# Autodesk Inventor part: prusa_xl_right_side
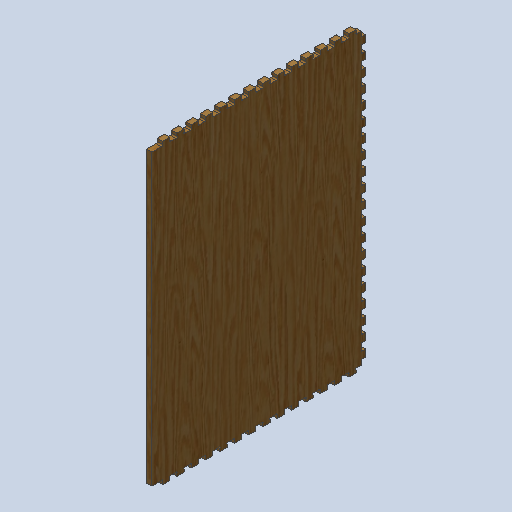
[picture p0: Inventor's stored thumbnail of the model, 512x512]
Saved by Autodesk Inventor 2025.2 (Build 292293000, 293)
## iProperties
Created: 2024-11
Part Number: prusa_xl_right_side
Material: Plywood, Finish
Document SubType Name: Modeling
Designer: BennF
Density: 0.552 g/cm^3
Appearance: Plywood - New
Author: BennF
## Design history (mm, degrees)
sketch "Sketch2"
  geometry: L1 (-351, 484.5)-(351, 484.5); L2 (351, 484.5)-(351, -484.5); L3 (351, -484.5)-(-351, -484.5); L4 (-351, -484.5)-(-351, 484.5); 3 further points
  constraints: 8 end point, 2 midpoint, 2 parallel, 1 horizontal, 1 horizontal alignment, 1 perpendicular, 1 vertical alignment
  dimensions: "d0" = 702 distance of L1.start L1.end (= prusa_xl_depth - finger_depth); "d1" = 969 distance of L3.end L1.start (= prusa_xl_height - 2 x finger_depth)
extrude "base_material" new body sketch "Sketch2" distance "d2" = 18 (= thickness); taper "d3" = 0 deg
sketch "Sketch3"
  geometry: L1 (-484.5, -314.9)-(-498, -314.9); L2 (-498, -314.9)-(-498, -291.1); L3 (-498, -291.1)-(-484.5, -291.1); L4 (0, -351)-(0, 351); L5 (-467.9, 351)-(-467.9, 364.5); L6 (-467.9, 364.5)-(-444.1, 364.5); L7 (-444.1, 364.5)-(-444.1, 351); L8 (-484.5, -266.9)-(-498, -266.9); L9 (-498, -266.9)-(-498, -243.1); L10 (-498, -243.1)-(-484.5, -243.1); L11 (-484.5, -218.9)-(-498, -218.9); L12 (-498, -218.9)-(-498, -195.1); L13 (-498, -195.1)-(-484.5, -195.1); L14 (-484.5, -170.9)-(-498, -170.9); L15 (-498, -170.9)-(-498, -147.1); L16 (-498, -147.1)-(-484.5, -147.1); L17 (-484.5, -122.9)-(-498, -122.9); L18 (-498, -122.9)-(-498, -99.1); L19 (-498, -99.1)-(-484.5, -99.1); L20 (-484.5, -74.9)-(-498, -74.9); L21 (-498, -74.9)-(-498, -51.1); L22 (-498, -51.1)-(-484.5, -51.1); L23 (-484.5, -26.9)-(-498, -26.9); L24 (-498, -26.9)-(-498, -3.1); L25 (-498, -3.1)-(-484.5, -3.1); L26 (-484.5, 21.1)-(-498, 21.1); L27 (-498, 21.1)-(-498, 44.9); L28 (-498, 44.9)-(-484.5, 44.9); L29 (-484.5, 69.1)-(-498, 69.1); L30 (-498, 69.1)-(-498, 92.9); L31 (-498, 92.9)-(-484.5, 92.9); L32 (-484.5, 117.1)-(-498, 117.1); L33 (-498, 117.1)-(-498, 140.9); L34 (-498, 140.9)-(-484.5, 140.9); L35 (-484.5, 165.1)-(-498, 165.1); L36 (-498, 165.1)-(-498, 188.9); L37 (-498, 188.9)-(-484.5, 188.9); L38 (-484.5, 213.1)-(-498, 213.1); L39 (-498, 213.1)-(-498, 236.9); L40 (-498, 236.9)-(-484.5, 236.9); L41 (-484.5, 261.1)-(-498, 261.1); L42 (-498, 261.1)-(-498, 284.9); L43 (-498, 284.9)-(-484.5, 284.9); L44 (-484.5, 309.1)-(-498, 309.1); L45 (-498, 309.1)-(-498, 332.9); L46 (-498, 332.9)-(-484.5, 332.9); L47 (498, 236.9)-(484.5, 236.9); L48 (484.5, 213.1)-(498, 213.1); L49 (498, 213.1)-(498, 236.9); L50 (498, 188.9)-(484.5, 188.9); L51 (484.5, 165.1)-(498, 165.1); L52 (498, 165.1)-(498, 188.9); L53 (484.5, 261.1)-(498, 261.1); L54 (498, 261.1)-(498, 284.9); L55 (498, 284.9)-(484.5, 284.9); L56 (484.5, 309.1)-(498, 309.1); L57 (498, 309.1)-(498, 332.9); L58 (498, 332.9)-(484.5, 332.9); L59 (484.5, -170.9)-(498, -170.9); L60 (498, -170.9)-(498, -147.1); L61 (498, -147.1)-(484.5, -147.1); L62 (484.5, -122.9)-(498, -122.9); L63 (498, -122.9)-(498, -99.1); L64 (498, -99.1)-(484.5, -99.1)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; 103 further points
  constraints: 290 end point, 76 horizontal alignment, 64 parallel, 59 symmetric about line, 52 vertical alignment, 32 collinear, 4 perpendicular, 1 horizontal, 1 midpoint, 1 vertical, 13 other
  dimensions: "d4" = 23.8 distance of L1.end L2.end (derived); "d13" = 23.8 distance of L5.end L6.end (derived); "d22" = 13.5 distance of L1.start L1.end (derived); "d23" = 13.5 distance of L5.start L5.end (derived); "d26" = 48 distance of L1.start L8.start (= finger_distance); "d33" = 48 distance of L5.start L91.start (= finger_distance); "d40" = 36.1 distance between parallel lines of L90 L1 (derived); "d41" = 30.1 distance between parallel lines of L5 L45 (derived)
extrude "joints_1" join sketch "Sketch3" distance "d38" = 18 (= thickness); taper "d39" = 0 deg
sketch "Sketch5"
  geometry: L1 (-40.167, -315)-(-21.967, -315); L2 (-21.967, -315)-(-21.967, -291); L3 (-21.967, -291)-(-40.167, -291); L4 (-40.167, -291)-(-40.167, -315); L5 (-484.5, -314.9)-(-484.5, -351) reference; L6 (222.367, -315)-(240.567, -315); L7 (240.567, -315)-(240.567, -291); L8 (240.567, -291)-(222.367, -291); L9 (222.367, -291)-(222.367, -315); L10 (-40.167, -267)-(-21.967, -267); L11 (-40.167, -243)-(-40.167, -267); L12 (-21.967, -243)-(-40.167, -243); L13 (-21.967, -267)-(-21.967, -243); L14 (222.367, -243)-(222.367, -267); L15 (222.367, -267)-(240.567, -267); L16 (240.567, -267)-(240.567, -243); L17 (240.567, -243)-(222.367, -243); L18 (-40.167, -219)-(-21.967, -219); L19 (-40.167, -195)-(-40.167, -219); L20 (-21.967, -195)-(-40.167, -195); L21 (-21.967, -219)-(-21.967, -195); L22 (222.367, -195)-(222.367, -219); L23 (222.367, -219)-(240.567, -219); L24 (240.567, -219)-(240.567, -195); L25 (240.567, -195)-(222.367, -195); L26 (-40.167, -171)-(-21.967, -171); L27 (-40.167, -147)-(-40.167, -171); L28 (-21.967, -147)-(-40.167, -147); L29 (-21.967, -171)-(-21.967, -147); L30 (222.367, -147)-(222.367, -171); L31 (222.367, -171)-(240.567, -171); L32 (240.567, -171)-(240.567, -147); L33 (240.567, -147)-(222.367, -147); L34 (-40.167, -123)-(-21.967, -123); L35 (-40.167, -99)-(-40.167, -123); L36 (-21.967, -99)-(-40.167, -99); L37 (-21.967, -123)-(-21.967, -99); L38 (222.367, -99)-(222.367, -123); L39 (222.367, -123)-(240.567, -123); L40 (240.567, -123)-(240.567, -99); L41 (240.567, -99)-(222.367, -99); L42 (-40.167, -75)-(-21.967, -75); L43 (-40.167, -51)-(-40.167, -75); L44 (-21.967, -51)-(-40.167, -51); L45 (-21.967, -75)-(-21.967, -51); L46 (222.367, -51)-(222.367, -75); L47 (222.367, -75)-(240.567, -75); L48 (240.567, -75)-(240.567, -51); L49 (240.567, -51)-(222.367, -51); L50 (-40.167, -27)-(-21.967, -27); L51 (-40.167, -3)-(-40.167, -27); L52 (-21.967, -3)-(-40.167, -3); L53 (-21.967, -27)-(-21.967, -3); L54 (222.367, -3)-(222.367, -27); L55 (222.367, -27)-(240.567, -27); L56 (240.567, -27)-(240.567, -3); L57 (240.567, -3)-(222.367, -3); L58 (-40.167, 21)-(-21.967, 21); L59 (-40.167, 45)-(-40.167, 21); L60 (-21.967, 45)-(-40.167, 45); L61 (-21.967, 21)-(-21.967, 45); L62 (222.367, 45)-(222.367, 21); L63 (222.367, 21)-(240.567, 21); L64 (240.567, 21)-(240.567, 45)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; 1 further point
  constraints: 224 end point, 4 parallel, 2 equal length, 2 horizontal, 2 perpendicular, 1 collinear, 1 horizontal alignment, 1 vertical, 207 other
  dimensions: "d59" = 24 distance of L3.end L1.start (= finger_width); "d60" = 18.2 distance of L1.start L1.end (derived); "d61" = 444.33333 distance between parallel lines of L5 L4 (= box_clearence_1 + box_height_1); "d62" = 244.33333 distance from line of L8.end L2 (= box_clearence_1 + box_height_2); "d65" = 48 distance of L1.start L10.start (= finger_distance); "d70" = 36 distance between parallel lines of L1 L114 (derived)
  node "Sketch Rectangular Pattern7" dims "d65" = 48 (= finger_distance), "d68" = 10
extrude "joints_2" cut sketch "Sketch5" distance "d71" = 13.5 (derived); taper "d72" = 0 deg
sketch "Sketch4" dims "d42" = 6 (= dogbone_diameter)
  geometry: L1 (484.5, -351)-(484.5, -314.9) reference; L2 (484.5, -314.9)-(498, -314.9) reference; L3 (498, -314.9)-(498, -291.1) reference; L4 (498, -291.1)-(484.5, -291.1) reference; L5 (484.5, -291.1)-(484.5, -266.9) reference; L6 (484.5, -266.9)-(498, -266.9) reference; L7 (498, -266.9)-(498, -243.1) reference; L8 (498, -243.1)-(484.5, -243.1) reference; L9 (484.5, -243.1)-(484.5, -218.9) reference; L10 (484.5, -218.9)-(498, -218.9) reference; L11 (498, -218.9)-(498, -195.1) reference; L12 (498, -195.1)-(484.5, -195.1) reference; L13 (484.5, -195.1)-(484.5, -170.9) reference; L14 (484.5, -170.9)-(498, -170.9) reference; L15 (498, -170.9)-(498, -147.1) reference; L16 (498, -147.1)-(484.5, -147.1) reference; L17 (484.5, -147.1)-(484.5, -122.9) reference; L18 (484.5, -122.9)-(498, -122.9) reference; L19 (498, -122.9)-(498, -99.1) reference; L20 (498, -99.1)-(484.5, -99.1) reference; L21 (484.5, -99.1)-(484.5, -74.9) reference; L22 (484.5, -74.9)-(498, -74.9) reference; L23 (498, -74.9)-(498, -51.1) reference; L24 (498, -51.1)-(484.5, -51.1) reference; L25 (484.5, -51.1)-(484.5, -26.9) reference; L26 (484.5, -26.9)-(498, -26.9) reference; L27 (498, -26.9)-(498, -3.1) reference; L28 (498, -3.1)-(484.5, -3.1) reference; L29 (484.5, -3.1)-(484.5, 21.1) reference; L30 (484.5, 21.1)-(498, 21.1) reference; L31 (498, 21.1)-(498, 44.9) reference; L32 (498, 44.9)-(484.5, 44.9) reference; L33 (484.5, 44.9)-(484.5, 69.1) reference; L34 (484.5, 69.1)-(498, 69.1) reference; L35 (498, 69.1)-(498, 92.9) reference; L36 (498, 92.9)-(484.5, 92.9) reference; L37 (484.5, 92.9)-(484.5, 117.1) reference; L38 (484.5, 117.1)-(498, 117.1) reference; L39 (498, 117.1)-(498, 140.9) reference; L40 (498, 140.9)-(484.5, 140.9) reference; L41 (484.5, 140.9)-(484.5, 165.1) reference; L42 (484.5, 165.1)-(498, 165.1) reference; L43 (498, 165.1)-(498, 188.9) reference; L44 (498, 188.9)-(484.5, 188.9) reference; L45 (484.5, 188.9)-(484.5, 213.1) reference; L46 (484.5, 213.1)-(498, 213.1) reference; L47 (498, 213.1)-(498, 236.9) reference; L48 (498, 236.9)-(484.5, 236.9) reference; L49 (484.5, 236.9)-(484.5, 261.1) reference; L50 (484.5, 261.1)-(498, 261.1) reference; L51 (498, 261.1)-(498, 284.9) reference; L52 (498, 284.9)-(484.5, 284.9) reference; L53 (484.5, 284.9)-(484.5, 309.1) reference; L54 (484.5, 309.1)-(498, 309.1) reference; L55 (498, 309.1)-(498, 332.9) reference; L56 (498, 332.9)-(484.5, 332.9) reference; L57 (484.5, 332.9)-(484.5, 351) reference; L58 (484.5, 351)-(467.9, 351) reference; L59 (467.9, 351)-(467.9, 364.5) reference; L60 (467.9, 364.5)-(444.1, 364.5) reference; L61 (444.1, 364.5)-(444.1, 351) reference; L62 (444.1, 351)-(419.9, 351) reference; L63 (419.9, 351)-(419.9, 364.5) reference; L64 (419.9, 364.5)-(396.1, 364.5) reference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; 258 further points
  constraints: 204 end point, 134 symmetric about line, 56 vertical, 40 horizontal, 30 point on line, 6 midpoint, 4 perpendicular, 2 collinear, 2 horizontal alignment, 2 vertical alignment, 598 other
  dimensions: "d45" = 48 distance of L190.end L202.end (= finger_distance); "d52" = 48 distance of point (-441.979, 353.121) point (-393.979, 353.121) (= finger_distance)
extrude "dogbones_1" cut sketch "Sketch4" distance "d57" = 18 (= thickness); taper "d58" = 0 deg
sketch "Sketch6" dims "d80" = 6 (derived)
  geometry: L1 (-488.743, -195.1)-(-498, -195.1) reference; L2 (-498, -195.1)-(-498, -218.9) reference; L3 (-498, -218.9)-(-488.743, -218.9) reference; L4 (-484.5, -223.143)-(-484.5, -238.857) reference; L5 (-488.743, -243.1)-(-498, -243.1) reference; L6 (-498, -243.1)-(-498, -266.9) reference; L7 (-498, -266.9)-(-488.743, -266.9) reference; L8 (-484.5, -271.143)-(-484.5, -286.857) reference; L9 (-488.743, -291.1)-(-498, -291.1) reference; L10 (-498, -291.1)-(-498, -314.9) reference; L11 (-498, -314.9)-(-488.743, -314.9) reference; L12 (-484.5, -319.143)-(-484.5, -351) reference; L13 (-484.5, -351)-(484.5, -351) reference; L14 (484.5, -351)-(484.5, -319.143) reference; L15 (488.743, -314.9)-(498, -314.9) reference; L16 (498, -314.9)-(498, -291.1) reference; L17 (498, -291.1)-(488.743, -291.1) reference; L18 (484.5, -286.857)-(484.5, -271.143) reference; L19 (488.743, -266.9)-(498, -266.9) reference; L20 (498, -266.9)-(498, -243.1) reference; L21 (498, -243.1)-(488.743, -243.1) reference; L22 (484.5, -238.857)-(484.5, -223.143) reference; L23 (488.743, -218.9)-(498, -218.9) reference; L24 (498, -218.9)-(498, -195.1) reference; L25 (498, -195.1)-(488.743, -195.1) reference; L26 (484.5, -190.857)-(484.5, -175.143) reference; L27 (488.743, -170.9)-(498, -170.9) reference; L28 (498, -170.9)-(498, -147.1) reference; L29 (498, -147.1)-(488.743, -147.1) reference; L30 (484.5, -142.857)-(484.5, -127.143) reference; L31 (488.743, -122.9)-(498, -122.9) reference; L32 (498, -122.9)-(498, -99.1) reference; L33 (498, -99.1)-(488.743, -99.1) reference; L34 (484.5, -94.857)-(484.5, -79.143) reference; L35 (488.743, -74.9)-(498, -74.9) reference; L36 (498, -74.9)-(498, -51.1) reference; L37 (498, -51.1)-(488.743, -51.1) reference; L38 (484.5, -46.857)-(484.5, -31.143) reference; L39 (488.743, -26.9)-(498, -26.9) reference; L40 (498, -26.9)-(498, -3.1) reference; L41 (498, -3.1)-(488.743, -3.1) reference; L42 (484.5, 1.143)-(484.5, 16.857) reference; L43 (488.743, 21.1)-(498, 21.1) reference; L44 (498, 21.1)-(498, 44.9) reference; L45 (498, 44.9)-(488.743, 44.9) reference; L46 (484.5, 49.143)-(484.5, 64.857) reference; L47 (488.743, 69.1)-(498, 69.1) reference; L48 (498, 69.1)-(498, 92.9) reference; L49 (498, 92.9)-(488.743, 92.9) reference; L50 (484.5, 97.143)-(484.5, 112.857) reference; L51 (488.743, 117.1)-(498, 117.1) reference; L52 (498, 117.1)-(498, 140.9) reference; L53 (498, 140.9)-(488.743, 140.9) reference; L54 (484.5, 145.143)-(484.5, 160.857) reference; L55 (488.743, 165.1)-(498, 165.1) reference; L56 (498, 165.1)-(498, 188.9) reference; L57 (498, 188.9)-(488.743, 188.9) reference; L58 (484.5, 193.143)-(484.5, 208.857) reference; L59 (488.743, 213.1)-(498, 213.1) reference; L60 (498, 213.1)-(498, 236.9) reference; L61 (498, 236.9)-(488.743, 236.9) reference; L62 (484.5, 241.143)-(484.5, 256.857) reference; L63 (488.743, 261.1)-(498, 261.1) reference; L64 (498, 261.1)-(498, 284.9) reference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; A1 r 3 centre (-486.621, -192.979) between (-488.743, -195.1) and (-484.5, -190.857) reference; A2 r 3 centre (-486.621, -221.021) between (-484.5, -223.143) and (-488.743, -218.9) reference; A3 r 3 centre (-486.621, -240.979) between (-488.743, -243.1) and (-484.5, -238.857) reference; A4 r 3 centre (-486.621, -269.021) between (-484.5, -271.143) and (-488.743, -266.9) reference; A5 r 3 centre (-486.621, -288.979) between (-488.743, -291.1) and (-484.5, -286.857) reference; A6 r 3 centre (-486.621, -317.021) between (-484.5, -319.143) and (-488.743, -314.9) reference; A7 r 3 centre (486.621, -317.021) between (488.743, -314.9) and (484.5, -319.143) reference; A8 r 3 centre (486.621, -288.979) between (484.5, -286.857) and (488.743, -291.1) reference; A9 r 3 centre (486.621, -269.021) between (488.743, -266.9) and (484.5, -271.143) reference; A10 r 3 centre (486.621, -240.979) between (484.5, -238.857) and (488.743, -243.1) reference; A11 r 3 centre (486.621, -221.021) between (488.743, -218.9) and (484.5, -223.143) reference; A12 r 3 centre (486.621, -192.979) between (484.5, -190.857) and (488.743, -195.1) reference; A13 r 3 centre (486.621, -173.021) between (488.743, -170.9) and (484.5, -175.143) reference; A14 r 3 centre (486.621, -144.979) between (484.5, -142.857) and (488.743, -147.1) reference; A15 r 3 centre (486.621, -125.021) between (488.743, -122.9) and (484.5, -127.143) reference; A16 r 3 centre (486.621, -96.979) between (484.5, -94.857) and (488.743, -99.1) reference; A17 r 3 centre (486.621, -77.021) between (488.743, -74.9) and (484.5, -79.143) reference; A18 r 3 centre (486.621, -48.979) between (484.5, -46.857) and (488.743, -51.1) reference; A19 r 3 centre (486.621, -29.021) between (488.743, -26.9) and (484.5, -31.143) reference; A20 r 3 centre (486.621, -0.979) between (484.5, 1.143) and (488.743, -3.1) reference; A21 r 3 centre (486.621, 18.979) between (488.743, 21.1) and (484.5, 16.857) reference; A22 r 3 centre (486.621, 47.021) between (484.5, 49.143) and (488.743, 44.9) reference; A23 r 3 centre (486.621, 66.979) between (488.743, 69.1) and (484.5, 64.857) reference; A24 r 3 centre (486.621, 95.021) between (484.5, 97.143) and (488.743, 92.9) reference; A25 r 3 centre (486.621, 114.979) between (488.743, 117.1) and (484.5, 112.857) reference; A26 r 3 centre (486.621, 143.021) between (484.5, 145.143) and (488.743, 140.9) reference; A27 r 3 centre (486.621, 162.979) between (488.743, 165.1) and (484.5, 160.857) reference; A28 r 3 centre (486.621, 191.021) between (484.5, 193.143) and (488.743, 188.9) reference; A29 r 3 centre (486.621, 210.979) between (488.743, 213.1) and (484.5, 208.857) reference; A30 r 3 centre (486.621, 239.021) between (484.5, 241.143) and (488.743, 236.9) reference; A31 r 3 centre (486.621, 258.979) between (488.743, 261.1) and (484.5, 256.857) reference; A32 r 3 centre (486.621, 287.021) between (484.5, 289.143) and (488.743, 284.9) reference; A33 r 3 centre (486.621, 306.979) between (488.743, 309.1) and (484.5, 304.857) reference; A34 r 3 centre (486.621, 335.021) between (484.5, 337.143) and (488.743, 332.9) reference; A35 r 3 centre (470.021, 353.121) between (467.9, 355.243) and (472.143, 351) reference; A36 r 3 centre (441.979, 353.121) between (439.857, 351) and (444.1, 355.243) reference; A37 r 3 centre (422.021, 353.121) between (419.9, 355.243) and (424.143, 351) reference; A38 r 3 centre (393.979, 353.121) between (391.857, 351) and (396.1, 355.243) reference; A39 r 3 centre (374.021, 353.121) between (371.9, 355.243) and (376.143, 351) reference; A40 r 3 centre (345.979, 353.121) between (343.857, 351) and (348.1, 355.243) reference; A41 r 3 centre (326.021, 353.121) between (323.9, 355.243) and (328.143, 351) reference; A42 r 3 centre (297.979, 353.121) between (295.857, 351) and (300.1, 355.243) reference; A43 r 3 centre (278.021, 353.121) between (275.9, 355.243) and (280.143, 351) reference; A44 r 3 centre (249.979, 353.121) between (247.857, 351) and (252.1, 355.243) reference; A45 r 3 centre (230.021, 353.121) between (227.9, 355.243) and (232.143, 351) reference; A46 r 3 centre (201.979, 353.121) between (199.857, 351) and (204.1, 355.243) reference; A47 r 3 centre (182.021, 353.121) between (179.9, 355.243) and (184.143, 351) reference; A48 r 3 centre (153.979, 353.121) between (151.857, 351) and (156.1, 355.243) reference; A49 r 3 centre (134.021, 353.121) between (131.9, 355.243) and (136.143, 351) reference; A50 r 3 centre (105.979, 353.121) between (103.857, 351) and (108.1, 355.243) reference; A51 r 3 centre (86.021, 353.121) between (83.9, 355.243) and (88.143, 351) reference; A52 r 3 centre (57.979, 353.121) between (55.857, 351) and (60.1, 355.243) reference; A53 r 3 centre (38.021, 353.121) between (35.9, 355.243) and (40.143, 351) reference; A54 r 3 centre (9.979, 353.121) between (7.857, 351) and (12.1, 355.243) reference; A55 r 3 centre (-9.979, 353.121) between (-12.1, 355.243) and (-7.857, 351) reference; A56 r 3 centre (-38.021, 353.121) between (-40.143, 351) and (-35.9, 355.243) reference; A57 r 3 centre (-57.979, 353.121) between (-60.1, 355.243) and (-55.857, 351) reference; A58 r 3 centre (-86.021, 353.121) between (-88.143, 351) and (-83.9, 355.243) reference; A59 r 3 centre (-105.979, 353.121) between (-108.1, 355.243) and (-103.857, 351) reference; A60 r 3 centre (-134.021, 353.121) between (-136.143, 351) and (-131.9, 355.243) reference; A61 r 3 centre (-153.979, 353.121) between (-156.1, 355.243) and (-151.857, 351) reference; A62 r 3 centre (-182.021, 353.121) between (-184.143, 351) and (-179.9, 355.243) reference; A63 r 3 centre (-201.979, 353.121) between (-204.1, 355.243) and (-199.857, 351) reference; A64 r 3 centre (-230.021, 353.121) between (-232.143, 351) and (-227.9, 355.243) reference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; 113 further points
  constraints: 112 end point, 112 point on line, 105 vertical, 596 other
  dimensions: "d83" = 48 distance of L277.start L314.end (derived)
extrude "dogbones_2" cut sketch "Sketch6" distance "d88" = 13.5 (derived); taper "d89" = 0 deg
mirror "Mirror1"
body "Solid1"
node "Sketch Rectangular Pattern3" dims "d26" = 48 (= finger_distance), "d29" = 10
node "Projected Loop1"
node "Sketch Rectangular Pattern4" dims "d33" = 48 (= finger_distance), "d36" = 10
node "Projected Loop2"
node "Sketch Rectangular Pattern5" dims "d45" = 48 (= finger_distance), "d48" = 10
node "Sketch Rectangular Pattern6" dims "d52" = 48 (= finger_distance), "d55" = 10
node "Projected Loop4"
node "Sketch Rectangular Pattern9" dims "d83" = 48 (derived), "d86" = 10
other parameters: "thickness" = 18 [user parameter; used in 3 equation terms], "finger_depth" = 18 [user parameter; used in 2 equation terms], "finger_width" = 24 [user parameter; used in 1 equation term], "finger_distance" = 48 [user parameter; used in 5 equation terms], "prusa_xl_depth" = 720 [user parameter; used in 1 equation term], "dogbone_diameter" = 6 [user parameter; used in 1 equation term], "prusa_xl_height" = 1005 [user parameter; used in 1 equation term], "prusa_xl_height_finger_distance" = 34.5 [user parameter], "prusa_xl_depth_finger_distance" = 36 [user parameter], "mill_bit" = 6 [user parameter], "dogbone_angle" = 45 deg [user parameter], "prusa_xl_width_finger_distance" = 36 [user parameter], "prusa_xl_shelf_depth" = 702 [user parameter], "prusa_xl_shelf_width" = 684 [user parameter], "box_clearence_1" = 9.33333 [user parameter; used in 2 equation terms], "box_height_1" = 435 [user parameter; used in 1 equation term], "box_height_2" = 235 [user parameter; used in 1 equation term], "hidden_depth" = 4.5 [user parameter], "connection_clearence" = 0.2 [user parameter], "sla_width" = 1296 [user parameter], "back_distance" = 5 [user parameter], "back_connection_depth" = 5 [user parameter], "storage_width_2" = 322 [user parameter], "box_clearence_2" = 24.33333 [user parameter], "shelf_depth_finger_distance" = 39 [user parameter], "connection_back_clearence" = 0 [user parameter], "thickness_back" = 6 [user parameter], "finger_depth_middle" = 8 [user parameter], "box_height_3" = 285 [user parameter], "bowden_tube_diameter" = 4 [user parameter], "connector_width_offset" = 105 [user parameter], "connector_width" = 26 [user parameter], "connector_depth" = 16 [user parameter]
